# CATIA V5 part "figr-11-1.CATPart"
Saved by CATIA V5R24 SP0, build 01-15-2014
Part number: Part1
Bounding box of the stored display mesh (mm): x -50 to 50, y -98.731 to 72.975, z 0 to 120
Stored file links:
  D:\KAVITA\CATIA V5-6R2014 Project_ Kavita\CATIA V5-6R2014_partfiles\Partfiles\c11_catia_v5-6r2014_prt\figr-11-1.CATPart
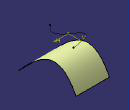
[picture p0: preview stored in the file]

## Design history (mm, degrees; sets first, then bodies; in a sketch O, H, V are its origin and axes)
Set1
  Sketch1 on yz-plane, origin (0, 0, 0), H (0, 1, 0), V (0, 0, 1)
    spline S1 through (-98.7309, 0) (-73.2816, 27.1192) (0, 74.8227) (72.975, 18.624)
    point P1 (-98.7309, 0)
    point P2 (0, 74.8227)
    coincidence: P1 H, P2 V
  Extrude1: Element1 Sketch1, Lim1 50, Lim2 50, Direction yz-plane
  Plane1: type Offset, RefPlane xy-plane, Offset 120
  Sketch2 on Plane1, origin (0, 0, 120), H (1, 0, 0), V (0, 1, 0)
    spline S1 through (28.7787, 44.6229) (-22.3035, 19.7059) (20.5049, -22.8447) (5.396, -48.9118)
Body1 (main body)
